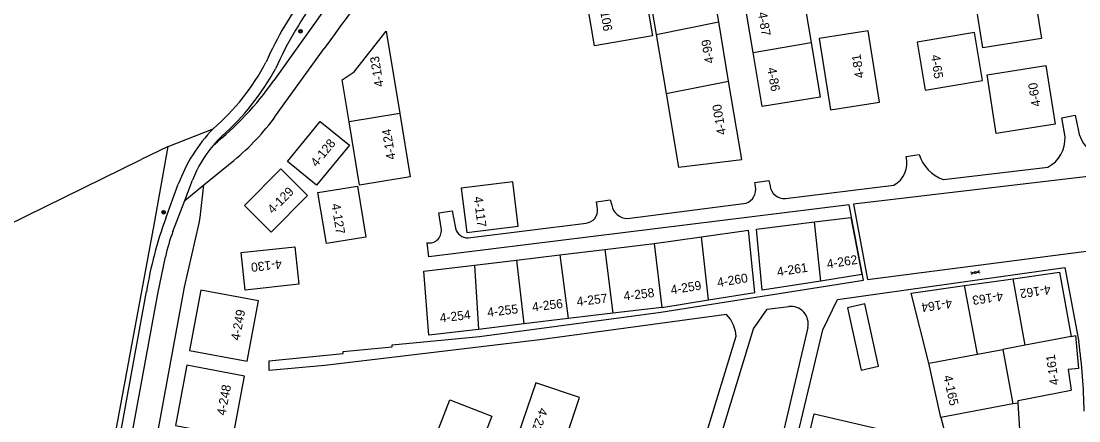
# Model space of a CAD drawing. Extents: x 134297 to 137000, y 403500 to 406000.
# Drawn here: x 136037.3 to 136271.5, y 405247.8 to 405336.3 of the extents above; entities that cross this region are included whole.
import ezdxf

# ---------------------------------------------------------------- set-up
doc = ezdxf.new("R2010")
doc.units = 0
for name, color, linetype in [('gg-afsc-draadraster', 7, 'Continuous'), ('gg-afsc-hekwerk', 7, 'Continuous'), ('gg-bbg-bijgebouw', 7, 'Continuous'), ('gg-knt-bronhoudergrens', 7, 'Continuous'), ('gg-knt-onverhard', 7, 'Continuous'), ('gg-knt-verharding', 7, 'Continuous'), ('gt-afsc-standplaatsafbakening', 7, 'Continuous'), ('gt-anno-standplaatsnummer', 7, 'Continuous'), ('gt-grn-groengrens', 7, 'Continuous'), ('gt-symb-boom', 7, 'Continuous'), ('gt-symb-gesloten verharding', 7, 'Continuous')]:
    doc.layers.add(name, color=color, linetype=linetype)

# ---------------------------------------------------------------- blocks, each defined once
blk = doc.blocks.new('gt0-BOOM')
at = {"layer": 'gt-symb-boom'}
for radius in [0.4, 0.2]:
    blk.add_circle((0, 0), radius, dxfattribs=at)
blk = doc.blocks.new('gt0-GESVH1')
at = {"layer": 'gt-symb-gesloten verharding'}
for p, q in [((-0.99, -0.26), (0.01, 0.24)), ((0.01, -0.26), (-0.99, 0.24)), ((0.01, 0.24), (1.01, -0.26)), ((1.01, 0.24), (0.01, -0.26))]:
    blk.add_line(p, q, dxfattribs=at)

msp = doc.modelspace()

# ---------------------------------------------------------------- linework, layer by layer
at = {"layer": 'gg-afsc-draadraster'}
msp.add_lwpolyline([(135973.8, 405294.24), (135981.02, 405284.41), (135990.64, 405269.41), (136000, 405274.3), (136063.94, 405305.66)], dxfattribs=at)
at = {"layer": 'gg-afsc-hekwerk'}
for p, q in [((136093.69, 405315.31), (136104.46, 405330.26)), ((136069.9, 405308.54), (136063.94, 405305.66)), ((136077.8, 405300.05), (136084.45, 405305.49))]:
    msp.add_line(p, q, dxfattribs=at)
for points in [[(136048.7, 405193.79), (136066.79, 405291.22), (136069.9, 405308.54)], [(136056.85, 405186.66), (136073.48, 405277.45), (136076.73, 405291.59), (136076.95, 405292.86), (136077.8, 405300.05)]]:
    msp.add_lwpolyline(points, dxfattribs=at)
for centre, radius, start, end in [((136708.09, 404895.71), 743.78, 141.71426, 144.25003), ((136051.74, 405345.51), 51.69, 309.2609, 324.2542)]:
    msp.add_arc(centre, radius, start, end, dxfattribs=at)
at = {"layer": 'gg-bbg-bijgebouw'}
msp.add_lwpolyline([(136224.16, 405273.72), (136220.32, 405272.86), (136223.36, 405259.08), (136227.21, 405259.93), (136224.16, 405273.72)], dxfattribs=at)
at = {"layer": 'gg-knt-bronhoudergrens'}
msp.add_line((136069.9, 405308.54), (136079.84, 405312.46), dxfattribs=at)
at = {"layer": 'gg-knt-onverhard'}
msp.add_lwpolyline([(136163.29, 405411.52), (136153.6, 405401.35), (136106.47, 405341.74), (136093.27, 405323.13)], dxfattribs=at)
msp.add_arc((136034.6, 405364.57), 71.83, 309.0354, 324.7688, dxfattribs=at)
at = {"layer": 'gg-knt-verharding'}
for p, q in [((136233.28, 405306.34), (136236.19, 405306.78)), ((136241.54, 405301.24), (136264.68, 405304.01)), ((136069.36, 405292.67), (136072.14, 405300.21)), ((136073.57, 405296.59), (136075.31, 405301.13)), ((136206.57, 405297.05), (136230.54, 405299.98)), ((136070.94, 405289.72), (136073.57, 405296.59)), ((136171.58, 405292.64), (136197.85, 405296.03)), ((136136.3, 405288.35), (136162.46, 405291.61)), ((136050.18, 405195.18), (136065.1, 405276.43)), ((136202.56, 405272.54), (136207.3, 405273.14))]:
    msp.add_line(p, q, dxfattribs=at)
for points in [[(136268.48, 405310.66), (136267.77, 405314.88), (136270.69, 405315.5), (136271.44, 405311.93)], [(136081.78, 405310.83), (136080.78, 405309.83), (136079.84, 405308.77)], [(136224.78, 405279.09), (136290.86, 405287.7), (136300.66, 405292.36), (136297.55, 405302.7), (136293.57, 405304.31), (136221.68, 405295.78), (136224.78, 405279.09)], [(136199.94, 405299.67), (136199.77, 405300.62), (136202.89, 405301.03), (136203.17, 405299.86)], [(136164.94, 405294.73), (136164.75, 405296.34), (136167.79, 405296.76), (136168.14, 405295.59)], [(136223.87, 405278.97), (136220.71, 405295.61), (136127.64, 405284.15), (136127.21, 405287.24)], [(136130.33, 405290.55), (136129.84, 405293.86), (136132.8, 405294.3), (136133.51, 405290.45)], [(136052.61, 405193.44), (136053.3, 405198.08), (136067.59, 405275.93), (136069.31, 405284.15)], [(136211.51, 405268.47), (136202.08, 405228.24), (136205.21, 405227.55), (136214.82, 405267.99), (136218.12, 405274.71), (136268.42, 405281.76), (136271.54, 405265.3)], [(136193.55, 405271.37), (136152.2, 405265.76), (136104.6, 405260.09), (136092.25, 405258.99), (136092.25, 405261.15), (136108.65, 405262.74), (136108.61, 405263.16), (136119.53, 405264.22), (136119.49, 405264.66), (136138.83, 405266.53), (136179.02, 405271.92), (136223.87, 405278.97)], [(136166.79, 405172.24), (136195.64, 405266.6), (136195.53, 405267.72), (136195.08, 405268.98), (136194.4, 405270.34), (136193.55, 405271.37)], [(136169.8, 405170.95), (136199.52, 405268.17), (136202.56, 405272.54)]]:
    msp.add_lwpolyline(points, dxfattribs=at)
for centre, radius, start, end in [((136161.34, 405296.39), 76.29, 142.6886, 156.1592), ((136168.17, 405292.72), 81.49, 142.4995, 156.0976), ((136047.24, 405350.36), 49.99, 310.707, 332.4331), ((136045.52, 405351.94), 54.81, 311.4105, 331.4426), ((136105.07, 405288.06), 35.1, 135.9562, 159.7493), ((136279.06, 405313.54), 7.78, 191.9199, 276.6121), ((136100.04, 405291.65), 26.49, 139.7207, 159.033), ((136261.51, 405310.23), 6.98, 296.9837, 3.5395), ((136227.94, 405304.87), 5.54, 298.0147, 15.3228), ((136244.36, 405309.32), 8.56, 197.2476, 250.7101), ((136196.82, 405299.04), 3.18, 288.8382, 11.3942), ((136206.29, 405300.17), 3.13, 185.669, 275.1158), ((136162.17, 405294.38), 2.79, 275.9448, 7.0636), ((136171.58, 405296.13), 3.49, 188.8288, 269.8726), ((136151.11, 405262.52), 87.13, 159.758, 170.8153), ((136104.97, 405276.7), 36.44, 159.0624, 168.2008), ((136127.66, 405289.94), 2.74, 260.4381, 13.0334), ((136136.16, 405291.07), 2.72, 193.1319, 272.8459), ((136207.78, 405269.34), 3.83, 346.8227, 97.229), ((136133.98, 405246.83), 138.79, 1.2961, 7.6476)]:
    msp.add_arc(centre, radius, start, end, dxfattribs=at)
at = {"layer": 'gt-afsc-standplaatsafbakening'}
for p, q in [((136191.79, 405336.12), (136189.58, 405349.19)), ((136175.71, 405346.42), (136177.92, 405333.35)), ((136210.12, 405344.11), (136212.24, 405331.55)), ((136199.43, 405329.39), (136197.3, 405341.94)), ((136177.92, 405333.35), (136191.79, 405336.12)), ((136194, 405323.04), (136191.79, 405336.12)), ((136177.92, 405333.35), (136180.13, 405320.28)), ((136199.43, 405329.39), (136212.24, 405331.55)), ((136212.24, 405331.55), (136214.29, 405319.44)), ((136180.13, 405320.28), (136194, 405323.04)), ((136121.16, 405315.84), (136109.98, 405314.01)), ((136121.16, 405315.84), (136123.45, 405301.87)), ((136112.27, 405300.03), (136109.98, 405314.01)), ((136123.45, 405301.87), (136112.27, 405300.03)), ((136187.96, 405288.55), (136198.4, 405290.02)), ((136200.16, 405290.24), (136213.03, 405291.86)), ((136214.39, 405278.77), (136213.03, 405291.86)), ((136177.53, 405287.08), (136187.96, 405288.55)), ((136189.51, 405274.59), (136187.96, 405288.55)), ((136156.6, 405284.57), (136166.56, 405285.76)), ((136166.56, 405285.76), (136177.53, 405287.08)), ((136166.56, 405285.76), (136168.39, 405271.65)), ((136177.53, 405287.08), (136179.22, 405272.95)), ((136137.74, 405282.31), (136147.04, 405283.43)), ((136147.04, 405283.43), (136156.6, 405284.57)), ((136147.04, 405283.43), (136148.64, 405269.29)), ((136156.6, 405284.57), (136158.47, 405270.47)), ((136126.52, 405280.97), (136137.74, 405282.31)), ((136137.74, 405282.31), (136138.6, 405268.09)), ((136246.23, 405277.76), (136257.01, 405279.28)), ((136259.67, 405264.6), (136257.01, 405279.28)), ((136249.09, 405262.6), (136246.23, 405277.76)), ((136179.22, 405272.95), (136189.51, 405274.59)), ((136168.39, 405271.65), (136158.47, 405270.47)), ((136179.22, 405272.95), (136168.39, 405271.65)), ((136148.64, 405269.29), (136138.6, 405268.09)), ((136158.47, 405270.47), (136148.64, 405269.29)), ((136269.84, 405266.53), (136259.67, 405264.6)), ((136259.67, 405264.6), (136254.69, 405263.66)), ((136238.33, 405260.58), (136249.09, 405262.6)), ((136249.09, 405262.6), (136254.69, 405263.66)), ((136254.69, 405263.66), (136256.96, 405251.57)), ((136240.99, 405248.56), (136238.33, 405260.58)), ((136256.96, 405251.57), (136240.99, 405248.56)), ((136258.12, 405251.76), (136256.96, 405251.57)), ((136258.78, 405240.65), (136258.12, 405251.76))]:
    msp.add_line(p, q, dxfattribs=at)
for points in [[(136162.02, 405344.38), (136174.84, 405346.54), (136177.12, 405333.02), (136164.3, 405330.86), (136162.02, 405344.38)], [(136250.27, 405330.42), (136248.22, 405343.42), (136261.22, 405345.47), (136263.27, 405332.47), (136250.27, 405330.42)], [(136216.53, 405316.67), (136227.39, 405318.38), (136224.9, 405334.18), (136214.04, 405332.47), (136216.53, 405316.67)], [(136109.98, 405314.01), (136108.46, 405323.29), (136111.07, 405325.07), (136118.17, 405334.09), (136121.16, 405315.84)], [(136235.72, 405331.63), (136237.52, 405321), (136250.2, 405323.15), (136248.4, 405333.78), (136235.72, 405331.63)], [(136214.29, 405319.44), (136201.45, 405317.41), (136199.43, 405329.39)], [(136253.27, 405311.43), (136251.21, 405324.43), (136264.21, 405326.48), (136266.27, 405313.48), (136253.27, 405311.43)], [(136180.13, 405320.28), (136182.88, 405304.01), (136196.94, 405305.65), (136194, 405323.04)], [(136102.76, 405299.97), (136096.31, 405305.26), (136103.58, 405314.11), (136110.03, 405308.82), (136102.76, 405299.97)], [(136092.69, 405289.61), (136086.78, 405295.49), (136094.85, 405303.61), (136100.77, 405297.73), (136092.69, 405289.61)], [(136113.7, 405288.5), (136104.92, 405287.07), (136103.07, 405298.37), (136111.85, 405299.81), (136113.7, 405288.5)], [(136136.02, 405289.52), (136147.42, 405290.95), (136146.18, 405300.77), (136134.78, 405299.33), (136136.02, 405289.52)], [(136213.03, 405291.86), (136221.05, 405292.87), (136223.47, 405280.2), (136214.39, 405278.77)], [(136189.51, 405274.59), (136199.8, 405276.24), (136198.4, 405290.02)], [(136214.39, 405278.77), (136201.4, 405276.73), (136200.16, 405290.24)], [(136086.96, 405276.78), (136086.06, 405285.08), (136097.96, 405286.36), (136098.86, 405278.07), (136086.96, 405276.78)], [(136138.6, 405268.09), (136127.64, 405266.78), (136126.52, 405280.97)], [(136257.01, 405279.28), (136267.26, 405280.72), (136269.84, 405266.53)], [(136077.16, 405276.79), (136074.63, 405263.44), (136087.4, 405261.02), (136089.93, 405274.37), (136077.16, 405276.79)], [(136238.33, 405260.58), (136234.42, 405276.09), (136246.23, 405277.76)], [(136269.84, 405266.53), (136270.83, 405266.72), (136271.43, 405259.4), (136269.2, 405259.22), (136269.83, 405254.6)], [(136074.02, 405260.18), (136071.49, 405246.83), (136084.26, 405244.41), (136086.79, 405257.76), (136074.02, 405260.18)], [(136151.3, 405256.29), (136146.46, 405242.01), (136156.17, 405238.72), (136161, 405253), (136151.3, 405256.29)], [(136258.12, 405251.76), (136258.08, 405252.34), (136269.83, 405254.6)], [(136126.71, 405238.17), (136132.24, 405252.47), (136141.58, 405248.85), (136136.04, 405234.55)], [(136209.27, 405233.9), (136212.91, 405249.42), (136227.87, 405245.91), (136227.64, 405244.92)], [(136240.99, 405248.56), (136243.49, 405239.22), (136244.31, 405239.29)]]:
    msp.add_lwpolyline(points, dxfattribs=at)
at = {"layer": 'gt-grn-groengrens'}
msp.add_line((136073.57, 405296.59), (136077.8, 405300.05), dxfattribs=at)

# ---------------------------------------------------------------- block references
at = {"layer": 'gt-symb-boom'}
for p in [(136099.2, 405334.07), (136068.89, 405294)]:
    msp.add_blockref('gt0-BOOM', p, dxfattribs=at)
at = {"layer": 'gt-symb-gesloten verharding', "rotation": -172.00768607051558}
msp.add_blockref('gt0-GESVH1', (136248.63, 405280.66), dxfattribs=at)

# ---------------------------------------------------------------- texts
at = {"layer": 'gt-anno-standplaatsnummer'}
for s, rotation, p in [('4-106', 279.591, (136165.18, 405340.68)), ('4-87', 279.591, (136200.48, 405338.15)), ('4-99', 99.591, (136190.78, 405327.1)), ('4-123', 99.3058, (136117.63, 405321.92)), ('4-81', 98.9621, (136224, 405323.82)), ('4-65', 277.9829, (136238.81, 405328.74)), ('4-86', 279.591, (136202.55, 405325.89)), ('4-60', 98.9621, (136263.1, 405317.52)), ('4-100', 99.591, (136193.45, 405311.29)), ('4-124', 99.3058, (136120.27, 405305.81)), ('4-128', 50.618, (136102.76, 405303.91)), ('4-129', 45.1541, (136093.07, 405293.53)), ('4-117', 277.1851, (136137.55, 405297.39)), ('4-127', 279.3058, (136106.03, 405295.77)), ('4-130', 186.1691, (136094.95, 405283.52)), ('4-261', 8.937, (136204.86, 405279.8)), ('4-262', 8.937, (136215.89, 405281.54)), ('4-260', 9.0763, (136191.61, 405277.46)), ('4-259', 9.0763, (136181.32, 405275.82)), ('4-257', 6.8267, (136160.47, 405273.22)), ('4-258', 6.8267, (136170.85, 405274.46)), ('4-163', 188.0399, (136254.62, 405276.41)), ('4-162', 188.0399, (136265.14, 405277.9)), ('4-255', 6.8267, (136140.67, 405270.85)), ('4-256', 6.8267, (136150.6, 405272.04)), ('4-164', 188.0399, (136243.33, 405274.82)), ('4-249', 79.2772, (136085.71, 405265.53)), ('4-254', 6.8267, (136130.16, 405269.6)), ('4-161', 97.8037, (136267.13, 405255.87)), ('4-165', 282.4859, (136241.52, 405257.73)), ('4-248', 79.2772, (136082.57, 405248.92)), ('4-221', 251.2869, (136152.11, 405250.88))]:
    msp.add_text(s, height=2, rotation=rotation, dxfattribs=at).set_placement(p)

doc.saveas('drawing.dxf')
